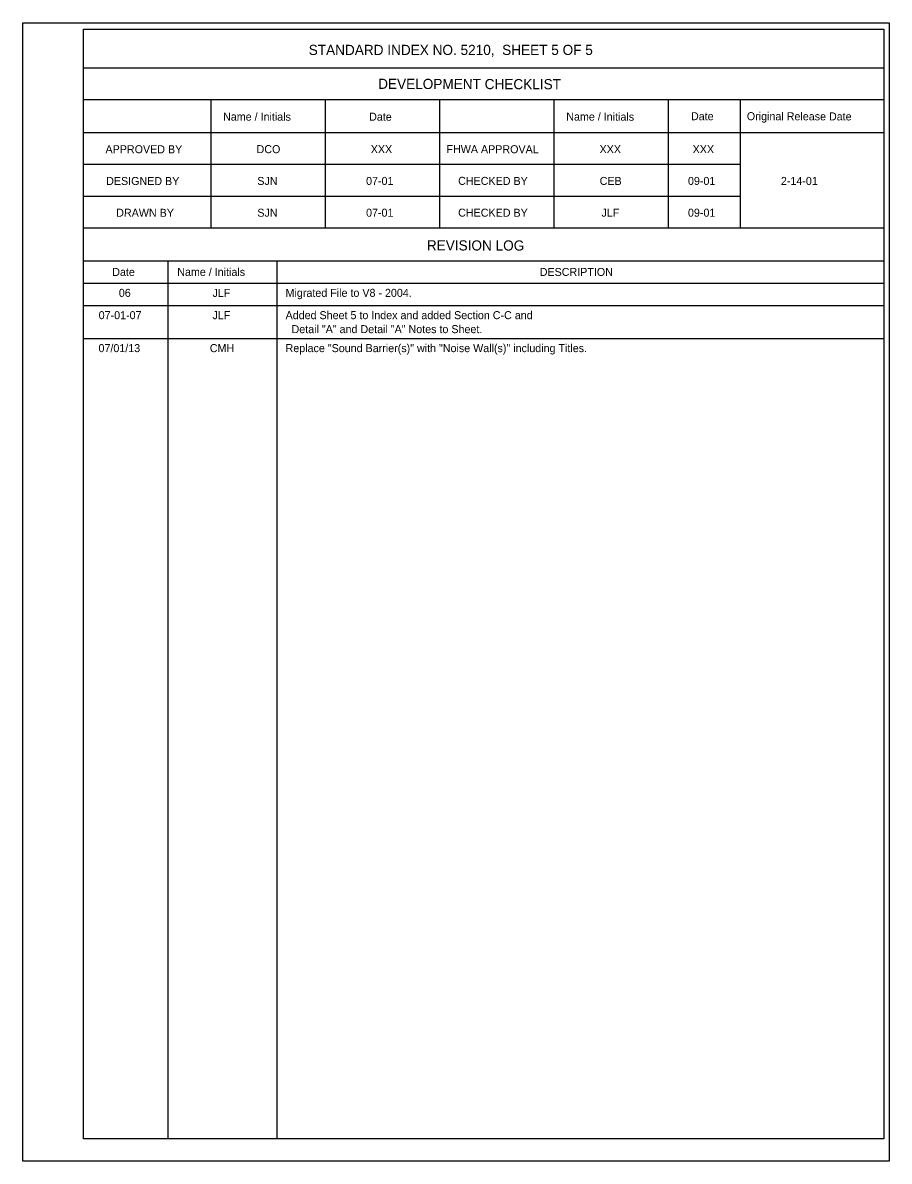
# Model space of a CAD drawing. Extents: x 120626.4 to 120668.8, y 120718.8 to 120735.5.
# Drawn here: x 120657.86 to 120668.77, y 120718.77 to 120733.1 of the extents above; entities that cross this region are included whole.
import ezdxf

# ---------------------------------------------------------------- set-up
doc = ezdxf.new("R2010")
doc.units = 0
for name, color, linetype in [('Border', 7, 'Continuous'), ('PlotBorder_dp', 7, 'Continuous'), ('TextStructures', 7, 'Continuous')]:
    doc.layers.add(name, color=color, linetype=linetype)

msp = doc.modelspace()

# ---------------------------------------------------------------- linework, layer by layer
at = {"layer": 'Border'}
for p, q in [((120668.701, 120732.529), (120658.628, 120732.529)), ((120668.701, 120732.129), (120658.628, 120732.129)), ((120660.228, 120732.129), (120660.228, 120730.515)), ((120661.668, 120732.129), (120661.668, 120730.515)), ((120663.108, 120732.129), (120663.108, 120730.515)), ((120664.548, 120732.129), (120664.548, 120730.515)), ((120665.988, 120732.129), (120665.988, 120730.515)), ((120666.895, 120732.129), (120666.895, 120730.515)), ((120668.701, 120731.715), (120658.628, 120731.715)), ((120666.895, 120731.315), (120658.628, 120731.315)), ((120666.895, 120730.915), (120658.628, 120730.915)), ((120668.701, 120730.515), (120658.628, 120730.515)), ((120668.701, 120730.101), (120658.628, 120730.101)), ((120659.688, 120730.101), (120659.688, 120719.048)), ((120661.059, 120730.101), (120661.059, 120719.048)), ((120668.701, 120729.819), (120658.628, 120729.819)), ((120668.701, 120729.538), (120658.628, 120729.538)), ((120668.701, 120729.123), (120658.628, 120729.123))]:
    msp.add_line(p, q, dxfattribs=at)
msp.add_lwpolyline([(120658.628, 120733.019), (120668.701, 120733.019), (120668.701, 120719.048), (120658.628, 120719.048)], close=True, dxfattribs=at)
at = {"layer": 'PlotBorder_dp'}
msp.add_line((120657.863, 120718.767), (120657.863, 120718.767), dxfattribs=at)
msp.add_lwpolyline([(120657.863, 120733.101), (120668.769, 120733.101), (120668.769, 120718.767), (120657.863, 120718.767)], close=True, dxfattribs=at)

# ---------------------------------------------------------------- texts
at = {"layer": 'TextStructures'}
for s, height, p in [('STANDARD INDEX NO. 5210,  SHEET 5 OF 5', 0.128, (120661.462, 120732.695)), ('DCO', 0.1008, (120660.806, 120731.459)), ('XXX', 0.1008, (120662.243, 120731.459)), ('XXX', 0.1008, (120665.123, 120731.459)), ('XXX', 0.1008, (120666.295, 120731.459)), ('SJN', 0.1008, (120660.815, 120731.059)), ('07-01', 0.1008, (120662.184, 120731.059)), ('CEB', 0.1008, (120665.125, 120731.059)), ('09-01', 0.1008, (120666.236, 120731.059)), ('2-14-01', 0.1008, (120667.406, 120731.059)), ('SJN', 0.1008, (120660.815, 120730.659)), ('07-01', 0.1008, (120662.184, 120730.659)), ('JLF', 0.1008, (120665.148, 120730.659)), ('09-01', 0.1008, (120666.236, 120730.659)), ('DESCRIPTION', 0.1008, (120664.37, 120729.913)), ('06', 0.1008, (120659.072, 120729.65)), ('JLF', 0.1008, (120660.251, 120729.65)), ('Migrated File to V8 - 2004.', 0.1008, (120661.171, 120729.65)), ('07-01-07', 0.1008, (120658.818, 120729.369)), ('JLF', 0.1008, (120660.251, 120729.369)), ('Added Sheet 5 to Index and added Section C-C and ', 0.1008, (120661.171, 120729.369)), ('  Detail "A" and Detail "A" Notes to Sheet.', 0.1008, (120661.171, 120729.193)), ('07/01/13', 0.1008, (120658.816, 120728.954)), ('CMH', 0.1008, (120660.217, 120728.954)), ('Replace "Sound Barrier(s)" with "Noise Wall(s)" including Titles.', 0.1008, (120661.171, 120728.954))]:
    msp.add_text(s, height=height, dxfattribs=at).set_placement(p)
for s, height, p in [('DEVELOPMENT CHECKLIST', 0.128, (120662.336, 120732.268)), ('Name / Initials', 0.1008, (120660.384, 120731.869)), ('Date', 0.1008, (120662.222, 120731.868)), ('Name / Initials', 0.1008, (120664.704, 120731.869)), ('Date', 0.1008, (120666.274, 120731.874)), ('Original Release Date', 0.1008, (120666.977, 120731.874)), ('APPROVED BY', 0.1008, (120658.904, 120731.459)), ('FHWA APPROVAL', 0.1008, (120663.196, 120731.46)), ('DESIGNED BY', 0.1008, (120658.912, 120731.059)), ('CHECKED BY', 0.1008, (120663.343, 120731.06)), ('DRAWN BY', 0.1008, (120659.039, 120730.659)), ('CHECKED BY', 0.1008, (120663.343, 120730.66)), ('REVISION LOG', 0.128, (120662.949, 120730.235)), ('Date', 0.1008, (120658.989, 120729.913)), ('Name / Initials', 0.1008, (120659.807, 120729.914))]:
    msp.add_text(s, height=height, rotation=359.8756, dxfattribs=at).set_placement(p)

doc.saveas('drawing.dxf')
